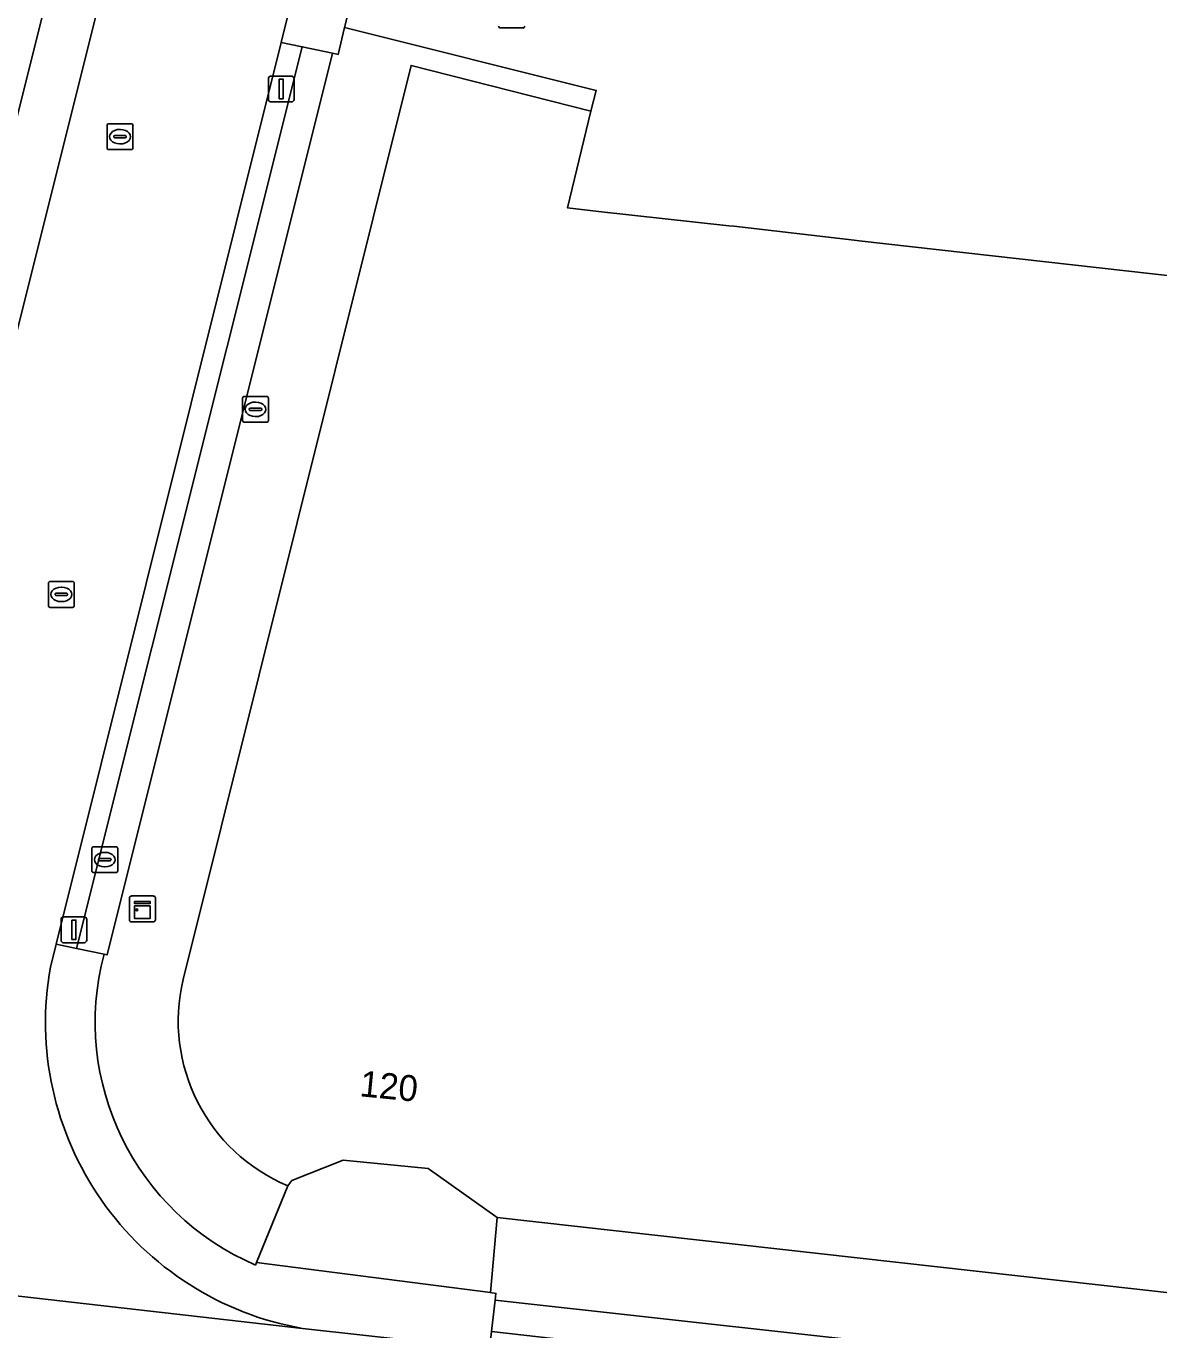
# Model space of a CAD drawing. Extents: x 161385 to 162589, y 388479 to 389756.
# Drawn here: x 162205.5 to 162249.2, y 388691.9 to 388742.2 of the extents above; entities that cross this region are included whole.
import ezdxf

# ---------------------------------------------------------------- set-up
doc = ezdxf.new("R2010")
doc.units = 0
for name, color, linetype in [('IMGEO_Berm_groen', 7, 'Continuous'), ('IMGEO_Brandkraan', 7, 'Continuous'), ('IMGEO_Erf', 7, 'Continuous'), ('IMGEO_Groenvoorziening', 7, 'Continuous'), ('IMGEO_Kast', 7, 'Continuous'), ('IMGEO_Lichtmast', 7, 'Continuous'), ('IMGEO_Loofbos', 7, 'Continuous'), ('IMGEO_Pand', 7, 'Continuous'), ('IMGEO_Pand_nummerreeks', 7, 'Continuous'), ('IMGEO_Rijbaan_lokaal_gesloten', 7, 'Continuous'), ('IMGEO_Rioolput', 7, 'Continuous'), ('IMGEO_Voetpad_open', 7, 'Continuous')]:
    doc.layers.add(name, color=color, linetype=linetype)

msp = doc.modelspace()

# ---------------------------------------------------------------- linework, layer by layer
at = {"layer": 'IMGEO_Berm_groen'}
for points in [[(162203.693, 388724.874), (162209.992, 388750), (162213.659, 388764.62), (162218.423, 388783.692), (162218.716, 388784.885)], [(162206.891, 388745.858), (162201.753, 388725.36), (162199.91, 388717.985), (162191.86, 388718.037), (162191.886, 388722.099), (162191.891, 388724.822), (162191.975, 388727.523), (162192.137, 388730.219), (162192.378, 388732.909), (162192.697, 388735.591), (162193.094, 388738.264), (162193.499, 388740.561), (162194.225, 388744.62)]]:
    msp.add_lwpolyline(points, dxfattribs=at)
msp.add_lwpolyline([(162216.116, 388741.439), (162215.296, 388741.611), (162206.618, 388706.811), (162207.403, 388706.644)], close=True, dxfattribs=at)
at = {"layer": 'IMGEO_Brandkraan'}
for p, q in [((162207.993, 388709.646), (162207.993, 388710.498)), ((162208.068, 388710.572), (162208.92, 388710.572)), ((162208.994, 388710.498), (162208.994, 388709.646)), ((162208.252, 388710.066), (162208.252, 388710.078)), ((162208.69, 388710.029), (162208.292, 388710.029)), ((162208.295, 388710.115), (162208.693, 388710.115)), ((162208.481, 388710.352), (162208.506, 388710.352)), ((162208.736, 388710.078), (162208.736, 388710.066)), ((162208.92, 388709.572), (162208.068, 388709.572)), ((162208.504, 388709.792), (162208.479, 388709.792))]:
    msp.add_line(p, q, dxfattribs=at)
for points in [[(162207.993, 388709.646), (162207.993, 388710.498)], [(162208.068, 388710.572), (162208.92, 388710.572)], [(162208.994, 388710.498), (162208.994, 388709.646)], [(162208.92, 388709.572), (162208.068, 388709.572)]]:
    msp.add_lwpolyline(points, dxfattribs=at)
for centre, radius, start, end in [((162208.07, 388710.496), 0.0765, 91.552, 178.448), ((162208.07, 388710.496), 0.0765, 91.552, 178.448), ((162208.918, 388710.496), 0.0765, 1.552, 88.448), ((162208.918, 388710.496), 0.0765, 1.552, 88.448), ((162208.292, 388710.075), 0.0403, 85.8775, 175.7526), ((162208.289, 388710.065), 0.0366, 178.938, 274.7102), ((162208.693, 388710.072), 0.043, 264.8664, 352.4533), ((162208.697, 388710.077), 0.0386, 1.7309, 96.639), ((162208.07, 388709.648), 0.0765, 181.552, 268.448), ((162208.07, 388709.648), 0.0765, 181.552, 268.448), ((162208.918, 388709.648), 0.0765, 271.552, 358.448), ((162208.918, 388709.648), 0.0765, 271.552, 358.448)]:
    msp.add_arc(centre, radius, start, end, dxfattribs=at)
for centre, major_axis, ratio, start_param, end_param in [((162208.48, 388710.072), (-0.387, 0.002), 0.722429, 4.712389, 7.853982), ((162208.505, 388710.072), (-0.39, 0.002), 0.717154, 1.570796, 4.712389)]:
    msp.add_ellipse(centre, major_axis=major_axis, ratio=ratio, start_param=start_param, end_param=end_param, dxfattribs=at)
at = {"layer": 'IMGEO_Erf'}
msp.add_lwpolyline([(162275.602, 388747.53), (162231.056, 388752.479), (162231.003, 388751.998), (162228.046, 388750), (162225.043, 388747.971), (162224.275, 388747.77), (162219.301, 388748.377), (162217.745, 388742.187), (162227.456, 388739.759), (162227.254, 388738.96), (162227.068, 388738.207), (162226.351, 388735.221), (162227.54, 388735.088), (162232.571, 388734.536), (162232.77, 388734.513), (162237.406, 388733.976), (162237.604, 388733.953), (162249.955, 388732.564)], dxfattribs=at)
at = {"layer": 'IMGEO_Groenvoorziening'}
for points in [[(162211.515, 388705.449), (162220.313, 388740.719), (162227.254, 388738.96), (162227.456, 388739.759), (162217.745, 388742.187), (162217.499, 388741.148), (162217.285, 388741.193), (162208.584, 388706.393), (162208.465, 388706.418)], [(162214.313, 388694.428), (162214.345, 388694.525), (162215.552, 388697.486)]]:
    msp.add_lwpolyline(points, dxfattribs=at)
msp.add_lwpolyline([(162249.57, 388690.204), (162249.919, 388693.319), (162223.633, 388696.259), (162223.374, 388693.364), (162223.587, 388693.331), (162223.557, 388693.066), (162248.149, 388690.348)], close=True, dxfattribs=at)
for centre, radius, start, end in [((162218.309, 388703.798), 10.186, 165.0954, 246.9052), ((162218.235, 388703.851), 6.908, 166.6251, 247.1422)]:
    msp.add_arc(centre, radius, start, end, dxfattribs=at)
at = {"layer": 'IMGEO_Kast'}
for p, q in [((162209.446, 388707.744), (162209.446, 388708.585)), ((162209.446, 388708.585), (162209.446, 388707.744)), ((162209.521, 388708.669), (162210.362, 388708.669)), ((162210.362, 388708.669), (162209.521, 388708.669)), ((162210.446, 388708.594), (162210.446, 388707.753)), ((162210.446, 388707.753), (162210.446, 388708.594)), ((162210.371, 388707.669), (162209.53, 388707.669)), ((162209.53, 388707.669), (162210.371, 388707.669))]:
    msp.add_line(p, q, dxfattribs=at)
for points in [[(162209.641, 388708.459), (162210.241, 388708.459), (162210.241, 388708.374), (162209.641, 388708.374), (162209.641, 388708.459)], [(162209.641, 388708.284), (162210.241, 388708.284), (162210.241, 388707.795), (162209.641, 388707.795), (162209.641, 388708.284)]]:
    msp.add_lwpolyline(points, dxfattribs=at)
msp.add_circle((162209.725, 388708.133), 0.0377, dxfattribs=at)
for centre, start, end in [((162209.524, 388708.591), 92.4484, 184.2845), ((162209.524, 388708.591), 92.4484, 184.2845), ((162210.368, 388708.591), 2.4484, 94.2845), ((162210.368, 388708.591), 2.4484, 94.2845), ((162209.524, 388707.747), 182.4484, 274.2845), ((162209.524, 388707.747), 182.4484, 274.2845), ((162210.368, 388707.747), 272.4484, 4.2845), ((162210.368, 388707.747), 272.4484, 4.2845)]:
    msp.add_arc(centre, 0.0779, start, end, dxfattribs=at)
at = {"layer": 'IMGEO_Lichtmast'}
for p, q in [((162214.808, 388739.41), (162214.808, 388740.21)), ((162214.808, 388740.21), (162214.808, 388739.41)), ((162214.908, 388740.31), (162215.698, 388740.31)), ((162215.698, 388740.31), (162214.908, 388740.31)), ((162215.798, 388740.21), (162215.798, 388739.41)), ((162215.798, 388739.41), (162215.798, 388740.21)), ((162215.698, 388739.31), (162214.908, 388739.31)), ((162214.908, 388739.31), (162215.698, 388739.31)), ((162206.907, 388707.867), (162207.697, 388707.867)), ((162207.697, 388707.867), (162206.907, 388707.867)), ((162206.807, 388706.967), (162206.807, 388707.767)), ((162206.807, 388707.767), (162206.807, 388706.967)), ((162207.797, 388707.767), (162207.797, 388706.967)), ((162207.797, 388706.967), (162207.797, 388707.767)), ((162207.697, 388706.867), (162206.907, 388706.867)), ((162206.907, 388706.867), (162207.697, 388706.867))]:
    msp.add_line(p, q, dxfattribs=at)
for points in [[(162215.228, 388740.185), (162215.378, 388740.185), (162215.378, 388739.435), (162215.228, 388739.435), (162215.228, 388740.185)], [(162207.227, 388707.742), (162207.377, 388707.742), (162207.377, 388706.992), (162207.227, 388706.992), (162207.227, 388707.742)]]:
    msp.add_lwpolyline(points, dxfattribs=at)
for centre, start, end in [((162214.908, 388740.21), 90, 180), ((162214.908, 388740.21), 90, 180), ((162215.698, 388740.21), 0, 90), ((162215.698, 388740.21), 360, 90), ((162214.908, 388739.41), 180, 270), ((162214.908, 388739.41), 180, 270), ((162215.698, 388739.41), 270, 0), ((162215.698, 388739.41), 270, 0), ((162206.907, 388707.767), 90, 180), ((162206.907, 388707.767), 90, 180), ((162207.697, 388707.767), 0, 90), ((162207.697, 388707.767), 360, 90), ((162206.907, 388706.967), 180, 270), ((162206.907, 388706.967), 180, 270), ((162207.697, 388706.967), 270, 0), ((162207.697, 388706.967), 270, 0)]:
    msp.add_arc(centre, 0.1, start, end, dxfattribs=at)
at = {"layer": 'IMGEO_Loofbos'}
msp.add_lwpolyline([(162194.225, 388744.62), (162193.499, 388740.561), (162193.094, 388738.264), (162192.697, 388735.591), (162192.378, 388732.909), (162192.137, 388730.219), (162191.975, 388727.523), (162191.891, 388724.822), (162191.886, 388722.099), (162191.86, 388718.037), (162199.91, 388717.985), (162201.753, 388725.36), (162206.891, 388745.858)], dxfattribs=at)
at = {"layer": 'IMGEO_Pand'}
msp.add_lwpolyline([(162215.552, 388697.486), (162215.711, 388697.693), (162217.697, 388698.472), (162220.967, 388698.149), (162223.633, 388696.259), (162249.919, 388693.319), (162250.682, 388700.177), (162255.335, 388699.679), (162258.899, 388731.55), (162258.439, 388731.604), (162254.514, 388732.048), (162249.955, 388732.564), (162237.604, 388733.953), (162237.406, 388733.976), (162232.77, 388734.513), (162232.571, 388734.536), (162227.54, 388735.088), (162226.351, 388735.221), (162227.068, 388738.207), (162227.254, 388738.96), (162220.313, 388740.719), (162211.515, 388705.449)], dxfattribs=at)
msp.add_arc((162218.235, 388703.851), 6.908, 166.6251, 247.1422, dxfattribs=at)
at = {"layer": 'IMGEO_Rijbaan_lokaal_gesloten'}
for points in [[(162215.296, 388741.611), (162217.225, 388749.348), (162217.388, 388750), (162225.506, 388782.552), (162218.716, 388784.885), (162218.423, 388783.692), (162213.659, 388764.62), (162209.992, 388750), (162203.693, 388724.874), (162198.604, 388704.506), (162198.376, 388703.539)], [(162206.396, 388705.918), (162206.618, 388706.811), (162215.296, 388741.611)], [(162353.423, 388676.578), (162317.536, 388680.643), (162316.844, 388680.72), (162297.525, 388682.881), (162285.793, 388684.193), (162285.607, 388684.214), (162265.796, 388686.429), (162255.908, 388687.535), (162247.951, 388688.424), (162223.34, 388691.176), (162216.117, 388691.984), (162185.651, 388695.455), (162184.144, 388695.622), (162173.399, 388696.814)], [(162185.651, 388695.455), (162216.117, 388691.984)]]:
    msp.add_lwpolyline(points, dxfattribs=at)
msp.add_arc((162218.198, 388703.794), 11.992, 169.7979, 260.0049, dxfattribs=at)
at = {"layer": 'IMGEO_Rioolput'}
for p, q in [((162224.621, 388742.166), (162223.769, 388742.166)), ((162208.581, 388737.546), (162208.581, 388738.398)), ((162208.656, 388738.472), (162209.508, 388738.472)), ((162209.069, 388738.252), (162209.094, 388738.252)), ((162209.582, 388738.398), (162209.582, 388737.546)), ((162208.84, 388737.966), (162208.84, 388737.978)), ((162209.278, 388737.929), (162208.88, 388737.929)), ((162208.883, 388738.015), (162209.281, 388738.015)), ((162209.092, 388737.692), (162209.067, 388737.692)), ((162209.324, 388737.978), (162209.324, 388737.966)), ((162209.508, 388737.472), (162208.656, 388737.472)), ((162213.809, 388727.024), (162213.809, 388727.876)), ((162213.884, 388727.95), (162214.736, 388727.95)), ((162214.111, 388727.493), (162214.509, 388727.493)), ((162214.297, 388727.73), (162214.322, 388727.73)), ((162214.81, 388727.876), (162214.81, 388727.024)), ((162214.068, 388727.444), (162214.068, 388727.456)), ((162214.506, 388727.407), (162214.108, 388727.407)), ((162214.32, 388727.17), (162214.295, 388727.17)), ((162214.552, 388727.456), (162214.552, 388727.444)), ((162214.736, 388726.95), (162213.884, 388726.95)), ((162206.317, 388719.882), (162206.317, 388720.734)), ((162206.392, 388720.808), (162207.244, 388720.808)), ((162206.805, 388720.588), (162206.83, 388720.588)), ((162207.318, 388720.734), (162207.318, 388719.882)), ((162206.576, 388720.302), (162206.576, 388720.314)), ((162207.014, 388720.265), (162206.616, 388720.265)), ((162206.619, 388720.351), (162207.017, 388720.351)), ((162206.828, 388720.028), (162206.803, 388720.028)), ((162207.06, 388720.314), (162207.06, 388720.302)), ((162207.244, 388719.808), (162206.392, 388719.808))]:
    msp.add_line(p, q, dxfattribs=at)
for points in [[(162224.621, 388742.166), (162223.769, 388742.166)], [(162208.581, 388737.546), (162208.581, 388738.398)], [(162208.656, 388738.472), (162209.508, 388738.472)], [(162209.582, 388738.398), (162209.582, 388737.546)], [(162209.508, 388737.472), (162208.656, 388737.472)], [(162213.809, 388727.024), (162213.809, 388727.876)], [(162213.884, 388727.95), (162214.736, 388727.95)], [(162214.81, 388727.876), (162214.81, 388727.024)], [(162214.736, 388726.95), (162213.884, 388726.95)], [(162206.317, 388719.882), (162206.317, 388720.734)], [(162206.392, 388720.808), (162207.244, 388720.808)], [(162207.318, 388720.734), (162207.318, 388719.882)], [(162207.244, 388719.808), (162206.392, 388719.808)]]:
    msp.add_lwpolyline(points, dxfattribs=at)
for centre, radius, start, end in [((162223.771, 388742.242), 0.0765, 181.552, 268.448), ((162223.771, 388742.242), 0.0765, 181.552, 268.448), ((162224.619, 388742.242), 0.0765, 271.552, 358.448), ((162224.619, 388742.242), 0.0765, 271.552, 358.448), ((162208.658, 388738.396), 0.0765, 91.552, 178.448), ((162208.658, 388738.396), 0.0765, 91.552, 178.448), ((162209.506, 388738.396), 0.0765, 1.552, 88.448), ((162209.506, 388738.396), 0.0765, 1.552, 88.448), ((162208.658, 388737.548), 0.0765, 181.552, 268.448), ((162208.658, 388737.548), 0.0765, 181.552, 268.448), ((162208.88, 388737.975), 0.0403, 85.8775, 175.7526), ((162208.877, 388737.965), 0.0366, 178.938, 274.7102), ((162209.281, 388737.972), 0.043, 264.8664, 352.4533), ((162209.285, 388737.977), 0.0386, 1.7309, 96.639), ((162209.506, 388737.548), 0.0765, 271.552, 358.448), ((162209.506, 388737.548), 0.0765, 271.552, 358.448), ((162213.886, 388727.874), 0.0765, 91.552, 178.448), ((162213.886, 388727.874), 0.0765, 91.552, 178.448), ((162214.108, 388727.453), 0.0403, 85.8775, 175.7526), ((162214.513, 388727.455), 0.0386, 1.7309, 96.639), ((162214.734, 388727.874), 0.0765, 1.552, 88.448), ((162214.734, 388727.874), 0.0765, 1.552, 88.448), ((162213.886, 388727.026), 0.0765, 181.552, 268.448), ((162213.886, 388727.026), 0.0765, 181.552, 268.448), ((162214.105, 388727.443), 0.0366, 178.938, 274.7102), ((162214.509, 388727.45), 0.043, 264.8664, 352.4533), ((162214.734, 388727.026), 0.0765, 271.552, 358.448), ((162214.734, 388727.026), 0.0765, 271.552, 358.448), ((162206.394, 388720.732), 0.0765, 91.552, 178.448), ((162206.394, 388720.732), 0.0765, 91.552, 178.448), ((162207.242, 388720.732), 0.0765, 1.552, 88.448), ((162207.242, 388720.732), 0.0765, 1.552, 88.448), ((162206.616, 388720.311), 0.0403, 85.8775, 175.7526), ((162206.613, 388720.301), 0.0366, 178.938, 274.7102), ((162207.017, 388720.308), 0.043, 264.8664, 352.4533), ((162207.021, 388720.313), 0.0386, 1.7309, 96.639), ((162206.394, 388719.884), 0.0765, 181.552, 268.448), ((162206.394, 388719.884), 0.0765, 181.552, 268.448), ((162207.242, 388719.884), 0.0765, 271.552, 358.448), ((162207.242, 388719.884), 0.0765, 271.552, 358.448)]:
    msp.add_arc(centre, radius, start, end, dxfattribs=at)
for centre, major_axis, ratio, start_param, end_param in [((162209.068, 388737.972), (-0.387, 0.002), 0.722429, 4.712389, 7.853982), ((162209.093, 388737.972), (-0.39, 0.002), 0.717154, 1.570796, 4.712389), ((162214.296, 388727.45), (-0.387, 0.002), 0.722429, 4.712389, 7.853982), ((162214.321, 388727.45), (-0.39, 0.002), 0.717154, 1.570796, 4.712389), ((162206.804, 388720.308), (-0.387, 0.002), 0.722429, 4.712389, 7.853982), ((162206.829, 388720.308), (-0.39, 0.002), 0.717154, 1.570796, 4.712389)]:
    msp.add_ellipse(centre, major_axis=major_axis, ratio=ratio, start_param=start_param, end_param=end_param, dxfattribs=at)
at = {"layer": 'IMGEO_Voetpad_open'}
for points in [[(162217.499, 388741.148), (162217.745, 388742.187), (162219.301, 388748.377), (162219.404, 388748.762), (162219.2, 388748.817), (162218.017, 388749.135), (162217.225, 388749.348), (162215.296, 388741.611), (162216.116, 388741.439), (162217.285, 388741.193)], [(162208.465, 388706.418), (162208.584, 388706.393), (162217.285, 388741.193), (162216.116, 388741.439), (162207.403, 388706.644)], [(162223.374, 388693.364), (162223.633, 388696.259), (162220.967, 388698.149), (162217.697, 388698.472), (162215.711, 388697.693), (162215.552, 388697.486), (162214.345, 388694.525), (162216.358, 388694.266)], [(162223.419, 388691.863), (162248.018, 388689.075), (162248.034, 388689.229), (162248.149, 388690.348), (162223.557, 388693.066), (162223.432, 388691.98)]]:
    msp.add_lwpolyline(points, close=True, dxfattribs=at)
for points in [[(162208.465, 388706.418), (162207.403, 388706.644), (162206.618, 388706.811), (162206.396, 388705.918)], [(162216.117, 388691.984), (162223.34, 388691.176), (162223.419, 388691.863), (162223.432, 388691.98), (162223.557, 388693.066), (162223.587, 388693.331), (162223.374, 388693.364), (162216.358, 388694.266), (162214.345, 388694.525), (162214.313, 388694.428)]]:
    msp.add_lwpolyline(points, dxfattribs=at)
for centre, radius, start, end in [((162218.309, 388703.798), 10.186, 165.0954, 246.9052), ((162218.198, 388703.794), 11.992, 169.7979, 260.0049)]:
    msp.add_arc(centre, radius, start, end, dxfattribs=at)

# ---------------------------------------------------------------- texts
at = {"layer": 'IMGEO_Pand_nummerreeks'}
msp.add_text('120', height=1, rotation=354.3588, dxfattribs=at).set_placement((162218.302, 388700.944))

doc.saveas('drawing.dxf')
